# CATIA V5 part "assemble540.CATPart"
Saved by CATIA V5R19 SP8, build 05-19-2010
Part number: cyl
Bounding box of the stored display mesh (mm): x -40 to 40, y -10 to 10, z -10 to 10
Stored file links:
  D:\Dropbox\CIAO82010_JCF\VIGUIER\0540-VIGUIER\CAO\assemble540.CATPart
  D:\Dropbox\CIAO82010_JCF\VIGUIER\0540-VIGUIER\CAO\0540.CATProduct
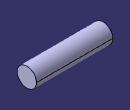
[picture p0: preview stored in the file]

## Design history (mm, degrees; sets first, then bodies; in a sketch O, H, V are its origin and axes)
External parameters (linked from other documents)
  External.rayon_assemblage = 10 mm
AxisSystem1: origin (0, 0, 0), X (1, 0, 0), Y (0, 1, 0), Z (0, 0, 1)
Body1 (main body)
  Sketch1 on YZ plane of AxisSystem1, origin (0, 0, 0), H (0, 1, 0), V (0, 0, 1)
    circle A1 centre (0, 0) radius 10
    radius A1 = 10 {= External.rayon_assemblage}
  Pad1: profile Sketch1, direction (1, 0, 0), length 40, mirrored extent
